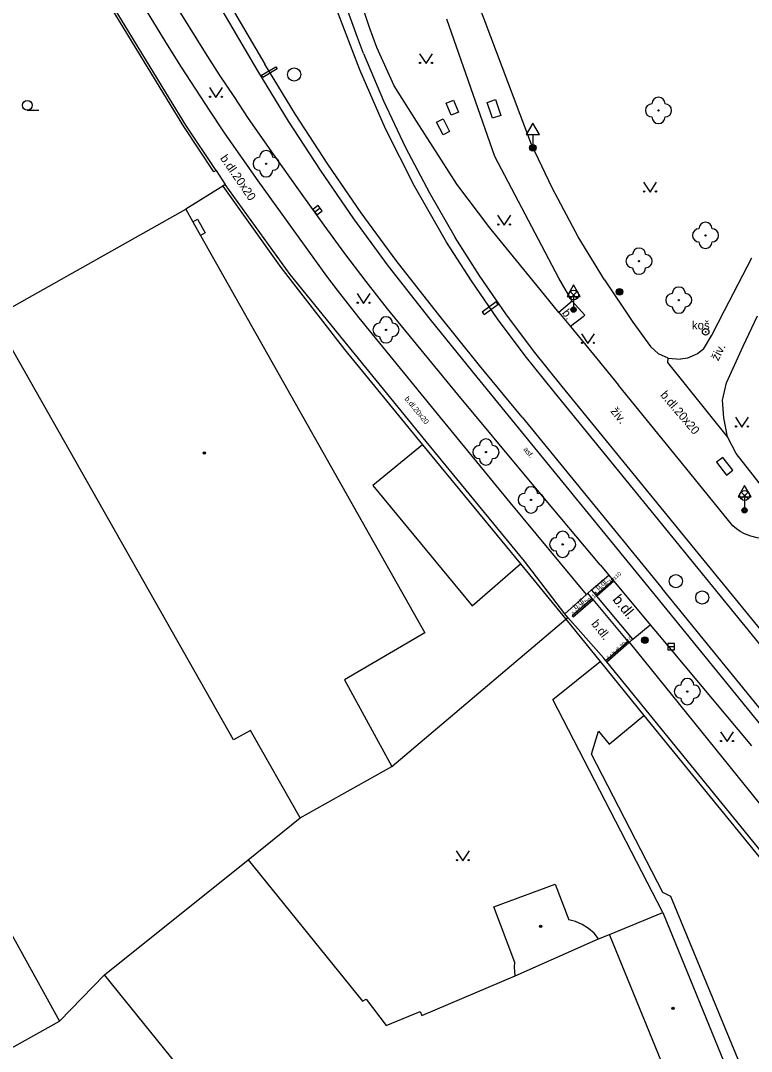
# Model space of a CAD drawing. Extents: x -600391 to -599491, y -1160176 to -1159402.
# Drawn here: x -599968.2 to -599912.4, y -1159894.2 to -1159815.5 of the extents above; entities that cross this region are included whole.
import ezdxf

# ---------------------------------------------------------------- set-up
doc = ezdxf.new("R2010")
doc.units = 0
for name, color, linetype in [('Level 10', 7, 'Continuous'), ('Level 11', 7, 'Continuous'), ('Level 13', 7, 'Continuous'), ('Level 22', 7, 'Continuous'), ('Level 24', 7, 'Continuous'), ('Level 25', 7, 'Continuous'), ('Level 26', 7, 'Continuous'), ('Level 27', 7, 'Continuous'), ('Level 33', 7, 'Continuous'), ('Level 34', 7, 'Continuous'), ('Level 36', 7, 'Continuous'), ('Level 39', 7, 'Continuous'), ('Level 40', 7, 'Continuous'), ('Level 42', 7, 'Continuous'), ('Level 5', 7, 'Continuous'), ('Level 7', 7, 'Continuous'), ('Level 8', 7, 'Continuous')]:
    doc.layers.add(name, color=color, linetype=linetype)

msp = doc.modelspace()

# ---------------------------------------------------------------- linework, layer by layer
at = {"layer": 'Level 10'}
for points in [[(-599936.04, -1159826.18), (-599937.94, -1159823.2), (-599939.66, -1159820.5), (-599940.98, -1159817.58), (-599941.54, -1159816.06), (-599942.03, -1159814.52), (-599942.52, -1159812.71), (-599943.22, -1159810.03), (-599943.39, -1159809.27), (-599943.93, -1159805.09)], [(-599950.76, -1159822.99), (-599951.87, -1159821.33), (-599952.97, -1159819.66), (-599954.05, -1159817.98), (-599956.51, -1159814.03)], [(-599944.99, -1159831.14), (-599945.71, -1159830.14), (-599946.93, -1159828.44), (-599948.85, -1159825.72), (-599950.76, -1159822.99)], [(-599928.52, -1159836.04), (-599932.34, -1159831.33), (-599934.86, -1159828.01), (-599936.04, -1159826.18)], [(-599940.15, -1159837.51), (-599941.8, -1159835.42), (-599943.42, -1159833.29), (-599944.99, -1159831.14)], [(-599927.08, -1159837.79), (-599928.52, -1159836.04)], [(-599923.93, -1159857.04), (-599929.38, -1159850.57), (-599934.79, -1159844.06), (-599940.15, -1159837.51)], [(-599923.93, -1159857.04), (-599929.38, -1159850.57), (-599934.79, -1159844.06), (-599940.15, -1159837.51)], [(-599927.08, -1159837.79), (-599926.2, -1159838.87)], [(-599926.2, -1159838.87), (-599924.2, -1159841.28), (-599922.53, -1159843.35)], [(-599916.76, -1159850.42), (-599922.53, -1159843.35)], [(-599913.81, -1159854.07), (-599916.76, -1159850.42)], [(-599912.92, -1159854.67), (-599913.24, -1159854.5), (-599913.53, -1159854.3), (-599913.81, -1159854.07)], [(-599912.44, -1159854.85), (-599912.92, -1159854.67)], [(-599911.43, -1159855.04), (-599911.56, -1159855.03), (-599911.94, -1159854.98), (-599912.44, -1159854.85)], [(-599923.93, -1159857.04), (-599923.27, -1159857.84), (-599922.94, -1159858.23), (-599922.88, -1159858.3), (-599920.11, -1159861.62)], [(-599920.11, -1159861.62), (-599919.42, -1159862.43)], [(-599919.42, -1159862.43), (-599912.37, -1159870.85)]]:
    msp.add_lwpolyline(points, dxfattribs=at)
at = {"layer": 'Level 11'}
for points in [[(-599963.14, -1159797.1), (-599955.3, -1159810.46), (-599950.08, -1159819.36)], [(-599929.17, -1159824.98), (-599933.64, -1159813.1), (-599938.33, -1159799.7)], [(-599955.87, -1159819.09), (-599956.94, -1159817.39), (-599958, -1159815.68), (-599959.04, -1159813.96), (-599965.39, -1159802.89)], [(-599941.98, -1159818.03), (-599942.44, -1159816.83), (-599942.88, -1159815.63), (-599943.31, -1159814.42)], [(-599931.96, -1159825.89), (-599935.62, -1159815.41)], [(-599941.98, -1159818.03), (-599940.46, -1159821.65), (-599938.79, -1159825.2), (-599936.96, -1159828.67), (-599935, -1159832.07)], [(-599952.59, -1159824.08), (-599953.7, -1159822.43), (-599954.79, -1159820.76), (-599955.87, -1159819.09)], [(-599950.08, -1159819.36), (-599947.75, -1159823.19), (-599945.31, -1159826.95), (-599942.76, -1159830.64), (-599940.11, -1159834.25)], [(-599949.78, -1159819.7), (-599948.67, -1159819.05)], [(-599949.68, -1159819.87), (-599949.78, -1159819.7)], [(-599948.57, -1159819.22), (-599949.68, -1159819.87)], [(-599948.67, -1159819.05), (-599948.57, -1159819.22)], [(-599943.98, -1159836.09), (-599944.78, -1159835.02), (-599947.42, -1159831.4), (-599950.02, -1159827.75), (-599952.59, -1159824.08)], [(-599923.59, -1159835.31), (-599925.62, -1159832.02), (-599927.59, -1159828.28), (-599929.17, -1159824.98)], [(-599927.08, -1159835.17), (-599931.96, -1159825.89)], [(-599952.73, -1159828.15), (-599955.55, -1159829.92)], [(-599955.01, -1159830.88), (-599954.66, -1159830.68)], [(-599954.66, -1159830.68), (-599954.07, -1159831.73)], [(-599954.07, -1159831.73), (-599954.42, -1159831.92)], [(-599926.82, -1159843.43), (-599929.02, -1159840.71), (-599931.12, -1159837.9), (-599933.11, -1159835.02), (-599935, -1159832.07)], [(-599915.4, -1159839.53), (-599914.44, -1159837.63), (-599912.35, -1159833.62)], [(-599940.11, -1159834.25), (-599936.92, -1159838.31), (-599933.68, -1159842.33), (-599930.41, -1159846.32)], [(-599926.06, -1159836.93), (-599927.08, -1159835.17)], [(-599923.59, -1159835.31), (-599921.43, -1159838.54)], [(-599942.33, -1159838.19), (-599943.16, -1159837.14), (-599943.98, -1159836.09)], [(-599931.87, -1159836.97), (-599932.93, -1159837.76)], [(-599931.72, -1159837.17), (-599931.87, -1159836.97)], [(-599926.06, -1159836.93), (-599927.08, -1159837.79)], [(-599926.06, -1159836.93), (-599925.1, -1159838), (-599925.23, -1159838.12)], [(-599932.93, -1159837.76), (-599932.78, -1159837.96)], [(-599932.78, -1159837.96), (-599931.72, -1159837.17)], [(-599924.98, -1159859.3), (-599930.79, -1159852.28), (-599936.57, -1159845.25), (-599942.33, -1159838.19)], [(-599925.23, -1159838.12), (-599926.2, -1159838.87)], [(-599921.43, -1159838.54), (-599920.09, -1159840.4)], [(-599914.29, -1159843.15), (-599913.03, -1159840.37), (-599911.92, -1159838.06)], [(-599916.04, -1159840.58), (-599915.4, -1159839.53)], [(-599918.73, -1159841.29), (-599919.47, -1159840.96), (-599920.09, -1159840.4)], [(-599916.04, -1159840.58), (-599916.5, -1159840.96), (-599917.26, -1159841.29), (-599917.8, -1159841.36)], [(-599914.22, -1159847.29), (-599918.76, -1159841.62), (-599918.73, -1159841.29)], [(-599918.73, -1159841.29), (-599917.8, -1159841.36)], [(-599914.22, -1159847.29), (-599914.5, -1159845.82), (-599914.6, -1159844.48), (-599914.29, -1159843.15)], [(-599878.58, -1159902.33), (-599881.68, -1159898.66), (-599890.08, -1159888.41), (-599897.94, -1159878.76), (-599907.81, -1159866.73), (-599916.46, -1159856.14), (-599926.82, -1159843.43)], [(-599930.41, -1159846.32), (-599919.73, -1159859.38), (-599911.26, -1159869.78), (-599901.58, -1159881.58), (-599893.26, -1159891.76), (-599885.63, -1159901.13), (-599882.18, -1159905.23)], [(-599937.5, -1159847.9), (-599941.28, -1159851), (-599933.71, -1159860.17), (-599930, -1159856.97)], [(-599913.55, -1159848.54), (-599914.22, -1159847.29)], [(-599909.94, -1159853.16), (-599913.55, -1159848.54)], [(-599924.98, -1159859.3), (-599924.87, -1159859.21), (-599924.58, -1159858.96), (-599923.27, -1159857.84)], [(-599924.98, -1159859.3), (-599924.87, -1159859.21), (-599924.58, -1159858.96), (-599923.27, -1159857.84)], [(-599922.94, -1159858.23), (-599924.24, -1159859.36)], [(-599922.94, -1159858.23), (-599924.24, -1159859.36)], [(-599921.44, -1159862.71), (-599924.18, -1159859.43), (-599924.24, -1159859.36), (-599924.58, -1159858.96)], [(-599924.18, -1159859.43), (-599922.88, -1159858.3)], [(-599924.18, -1159859.43), (-599922.88, -1159858.3)], [(-599924.98, -1159859.3), (-599926.62, -1159860.77)], [(-599924.54, -1159859.61), (-599926.06, -1159860.93)], [(-599926, -1159861.01), (-599924.47, -1159859.69)], [(-599921.74, -1159862.96), (-599921.8, -1159862.89), (-599924.47, -1159859.69), (-599924.54, -1159859.61), (-599924.87, -1159859.21)], [(-599939.83, -1159872.43), (-599926.54, -1159861.18)], [(-599926.54, -1159861.18), (-599926.4, -1159861.06)], [(-599926, -1159861.01), (-599926.06, -1159860.93)], [(-599899.77, -1159890.08), (-599904.44, -1159884.3), (-599914.02, -1159872.44), (-599921.7, -1159862.93), (-599921.44, -1159862.71), (-599920.11, -1159861.62)], [(-599899.77, -1159890.08), (-599904.44, -1159884.3), (-599914.02, -1159872.44), (-599921.7, -1159862.93), (-599921.44, -1159862.71), (-599920.11, -1159861.62)], [(-599921.8, -1159862.89), (-599923.49, -1159864.37)], [(-599923.43, -1159864.44), (-599921.74, -1159862.96), (-599921.7, -1159862.93)], [(-599919.16, -1159883.57), (-599927.54, -1159867.32), (-599923.93, -1159864.42)], [(-599913.1, -1159895.5), (-599918.54, -1159882.33), (-599919.14, -1159882.04), (-599924.58, -1159871.49), (-599924.05, -1159869.73), (-599923.24, -1159870.71), (-599920.59, -1159868.53)], [(-599950.79, -1159879.55), (-599946.83, -1159876.34)], [(-599965.19, -1159891.85), (-599961.76, -1159888.32)]]:
    msp.add_lwpolyline(points, dxfattribs=at)
at = {"layer": 'Level 13'}
for points in [[(-599954.67, -1159810.08), (-599949.51, -1159818.86)], [(-599935.65, -1159832.43), (-599938.09, -1159828.17), (-599940.3, -1159823.78), (-599942.28, -1159819.29), (-599944.02, -1159814.7)], [(-599939.5, -1159833.83), (-599942.16, -1159830.19), (-599944.72, -1159826.49), (-599947.17, -1159822.7), (-599949.51, -1159818.86)], [(-599931.76, -1159838.29), (-599933.76, -1159835.39), (-599935.65, -1159832.43)], [(-599929.89, -1159845.79), (-599933.14, -1159841.83), (-599936.34, -1159837.85), (-599939.5, -1159833.82)], [(-599927.44, -1159843.85), (-599929.65, -1159841.11), (-599931.76, -1159838.29)], [(-599882.25, -1159899.15), (-599890.61, -1159888.94), (-599898.53, -1159879.23), (-599908.38, -1159867.2), (-599917.02, -1159856.63), (-599927.45, -1159843.85)], [(-599929.89, -1159845.78), (-599919.19, -1159858.86)], [(-599901, -1159881.13), (-599910.7, -1159869.27), (-599919.19, -1159858.86)]]:
    msp.add_lwpolyline(points, dxfattribs=at)
at = {"layer": 'Level 22'}
for centre in [(-599919.48, -1159822.38), (-599949.42, -1159826.45), (-599915.89, -1159831.91), (-599920.96, -1159833.88), (-599917.93, -1159836.85), (-599940.27, -1159839.12), (-599932.65, -1159848.44), (-599929.2, -1159852.09), (-599926.79, -1159855.48), (-599917.28, -1159866.71)]:
    msp.add_circle(centre, 0.05, dxfattribs=at)
for centre, start, end in [((-599919.98, -1159822.38), 90, 270), ((-599919.48, -1159821.88), 0, 180), ((-599918.98, -1159822.38), 270, 90), ((-599919.48, -1159822.88), 180, 0), ((-599949.92, -1159826.45), 90, 270), ((-599949.42, -1159825.95), 0, 180), ((-599948.92, -1159826.45), 270, 90), ((-599949.42, -1159826.95), 180, 0), ((-599916.39, -1159831.91), 90, 270), ((-599915.89, -1159831.41), 0, 180), ((-599915.39, -1159831.91), 270, 90), ((-599920.96, -1159833.38), 0, 180), ((-599915.89, -1159832.41), 180, 0), ((-599921.46, -1159833.88), 90, 270), ((-599920.46, -1159833.88), 270, 90), ((-599920.96, -1159834.38), 180, 0), ((-599917.93, -1159836.35), 0, 180), ((-599918.43, -1159836.85), 90, 270), ((-599917.43, -1159836.85), 270, 90), ((-599917.93, -1159837.35), 180, 0), ((-599940.77, -1159839.12), 90, 270), ((-599940.27, -1159838.62), 0, 180), ((-599939.77, -1159839.12), 270, 90), ((-599940.27, -1159839.62), 180, 0), ((-599933.15, -1159848.44), 90, 270), ((-599932.65, -1159847.94), 0, 180), ((-599932.15, -1159848.44), 270, 90), ((-599932.65, -1159848.94), 180, 0), ((-599929.2, -1159851.59), 0, 180), ((-599929.7, -1159852.09), 90, 270), ((-599928.7, -1159852.09), 270, 90), ((-599929.2, -1159852.59), 180, 0), ((-599927.29, -1159855.48), 90, 270), ((-599926.79, -1159854.98), 0, 180), ((-599926.29, -1159855.48), 270, 90), ((-599926.79, -1159855.98), 180, 0), ((-599917.28, -1159866.21), 0, 180), ((-599917.78, -1159866.71), 90, 270), ((-599916.78, -1159866.71), 270, 90), ((-599917.28, -1159867.21), 180, 0)]:
    msp.add_arc(centre, 0.5, start, end, dxfattribs=at)
at = {"layer": 'Level 24'}
for points in [[(-599935.29, -1159822.74), (-599935.68, -1159821.82), (-599935.12, -1159821.59), (-599934.74, -1159822.51), (-599935.29, -1159822.74)], [(-599936.42, -1159823.28), (-599935.92, -1159823.02)], [(-599935.92, -1159824.24), (-599936.42, -1159823.28)], [(-599935.92, -1159823.02), (-599935.42, -1159823.98)], [(-599935.42, -1159823.98), (-599935.92, -1159824.24)]]:
    msp.add_lwpolyline(points, dxfattribs=at)
at = {"layer": 'Level 25'}
for centre, radius in [((-599929.07, -1159825.24), 0.25), ((-599929.07, -1159825.24), 0.2), ((-599929.07, -1159825.24), 0.15), ((-599929.07, -1159825.24), 0.1), ((-599929.07, -1159825.24), 0.05), ((-599922.45, -1159836.22), 0.25), ((-599922.45, -1159836.22), 0.2), ((-599922.45, -1159836.22), 0.15), ((-599922.45, -1159836.22), 0.1), ((-599922.45, -1159836.22), 0.05), ((-599915.88, -1159839.27), 0.25), ((-599915.88, -1159839.27), 0.0303), ((-599920.53, -1159862.79), 0.25), ((-599920.53, -1159862.79), 0.2), ((-599920.53, -1159862.79), 0.15), ((-599920.53, -1159862.79), 0.1), ((-599920.53, -1159862.79), 0.05)]:
    msp.add_circle(centre, radius, dxfattribs=at)
at = {"layer": 'Level 26'}
for points in [[(-599932.55, -1159821.78), (-599931.92, -1159821.56)], [(-599932.14, -1159822.98), (-599932.55, -1159821.78)], [(-599931.92, -1159821.56), (-599931.51, -1159822.76)], [(-599931.51, -1159822.76), (-599932.14, -1159822.98)], [(-599914.57, -1159848.85), (-599915.05, -1159849.22)], [(-599915.05, -1159849.22), (-599914.28, -1159850.2)], [(-599913.8, -1159849.83), (-599914.57, -1159848.85)], [(-599914.28, -1159850.2), (-599913.8, -1159849.83)]]:
    msp.add_lwpolyline(points, dxfattribs=at)
at = {"layer": 'Level 27'}
for p, q in [((-599945.301, -1159829.839), (-599945.699, -1159830.141)), ((-599918.77, -1159863.28), (-599918.27, -1159863.28))]:
    msp.add_line(p, q, dxfattribs=at)
for points in [[(-599945.452, -1159829.64), (-599945.85, -1159829.942), (-599945.548, -1159830.34), (-599945.15, -1159830.038)], [(-599918.77, -1159863.53), (-599918.27, -1159863.53), (-599918.27, -1159863.03), (-599918.77, -1159863.03)]]:
    msp.add_lwpolyline(points, close=True, dxfattribs=at)
for centre in [(-599947.28, -1159819.64), (-599918.16, -1159858.29), (-599916.14, -1159859.53)]:
    msp.add_circle(centre, 0.5, dxfattribs=at)
at = {"layer": 'Level 33'}
for p, q in [((-599926.225, -1159836.72), (-599925.695, -1159836.19)), ((-599926.225, -1159836.19), (-599925.695, -1159836.72)), ((-599925.96, -1159836.83), (-599925.96, -1159837.58)), ((-599913.175, -1159852.02), (-599912.645, -1159851.49)), ((-599913.175, -1159851.49), (-599912.645, -1159852.02)), ((-599912.91, -1159852.13), (-599912.91, -1159852.88))]:
    msp.add_line(p, q, dxfattribs=at)
for centre, radius in [((-599925.96, -1159836.455), 0.375), ((-599925.96, -1159837.58), 0.2), ((-599925.96, -1159837.58), 0.145), ((-599925.96, -1159837.58), 0.0876), ((-599912.91, -1159851.755), 0.375), ((-599912.91, -1159852.88), 0.2), ((-599912.91, -1159852.88), 0.145), ((-599912.91, -1159852.88), 0.0876)]:
    msp.add_circle(centre, radius, dxfattribs=at)
at = {"layer": 'Level 34'}
for p, q in [((-599929.07, -1159824.222), (-599929.07, -1159825.24)), ((-599929.32, -1159825.24), (-599928.82, -1159825.24)), ((-599925.96, -1159836.562), (-599925.96, -1159837.58)), ((-599912.91, -1159851.862), (-599912.91, -1159852.88))]:
    msp.add_line(p, q, dxfattribs=at)
for points in [[(-599929.57, -1159824.222), (-599928.57, -1159824.222), (-599929.07, -1159823.356)], [(-599926.46, -1159836.562), (-599925.46, -1159836.562), (-599925.96, -1159835.696)], [(-599913.41, -1159851.862), (-599912.41, -1159851.862), (-599912.91, -1159850.996)]]:
    msp.add_lwpolyline(points, close=True, dxfattribs=at)
at = {"layer": 'Level 36'}
msp.add_line((-599967.65, -1159822.365), (-599966.775, -1159822.365), dxfattribs=at)
for points in [[(-599937.72, -1159818.06), (-599937.22, -1159818.81), (-599936.72, -1159818.06)], [(-599953.75, -1159820.64), (-599953.25, -1159821.39), (-599952.75, -1159820.64)], [(-599920.62, -1159827.86), (-599920.12, -1159828.61), (-599919.62, -1159827.86)], [(-599931.76, -1159830.38), (-599931.26, -1159831.13), (-599930.76, -1159830.38)], [(-599942.48, -1159836.35), (-599941.98, -1159837.1), (-599941.48, -1159836.35)], [(-599925.36, -1159839.41), (-599924.86, -1159840.16), (-599924.36, -1159839.41)], [(-599913.61, -1159845.78), (-599913.11, -1159846.53), (-599912.61, -1159845.78)], [(-599914.75, -1159869.78), (-599914.25, -1159870.53), (-599913.75, -1159869.78)], [(-599934.91, -1159878.87), (-599934.41, -1159879.62), (-599933.91, -1159878.87)]]:
    msp.add_lwpolyline(points, dxfattribs=at)
for centre, radius in [((-599937.67, -1159818.76), 0.05), ((-599936.771, -1159818.76), 0.05), ((-599953.7, -1159821.34), 0.05), ((-599952.801, -1159821.34), 0.05), ((-599967.65, -1159821.99), 0.375), ((-599920.57, -1159828.56), 0.05), ((-599919.671, -1159828.56), 0.05), ((-599931.71, -1159831.08), 0.05), ((-599930.811, -1159831.08), 0.05), ((-599942.43, -1159837.05), 0.05), ((-599941.531, -1159837.05), 0.05), ((-599925.31, -1159840.11), 0.05), ((-599924.411, -1159840.11), 0.05), ((-599913.56, -1159846.48), 0.05), ((-599912.661, -1159846.48), 0.05), ((-599914.7, -1159870.48), 0.05), ((-599913.801, -1159870.48), 0.05), ((-599934.86, -1159879.57), 0.05), ((-599933.961, -1159879.57), 0.05)]:
    msp.add_circle(centre, radius, dxfattribs=at)
at = {"layer": 'Level 39'}
for centre, radius in [((-599954.13, -1159848.51), 0.09), ((-599954.13, -1159848.51), 0.0398), ((-599928.48, -1159884.62), 0.09), ((-599928.48, -1159884.62), 0.0398), ((-599918.38, -1159890.88), 0.09), ((-599918.38, -1159890.88), 0.0398)]:
    msp.add_circle(centre, radius, dxfattribs=at)
at = {"layer": 'Level 5'}
for points in [[(-599969.46, -1159837.75), (-599955.55, -1159829.92)], [(-599955.55, -1159829.92), (-599955.01, -1159830.88)], [(-599955.01, -1159830.88), (-599954.42, -1159831.92)], [(-599954.42, -1159831.92), (-599937.3, -1159862.24)], [(-599951.91, -1159870.4), (-599969.1, -1159840.07)], [(-599937.3, -1159862.24), (-599943.43, -1159865.82)], [(-599943.43, -1159865.82), (-599939.83, -1159872.43)], [(-599950.61, -1159869.69), (-599951.91, -1159870.4)], [(-599946.83, -1159876.34), (-599950.61, -1159869.69)], [(-599946.83, -1159876.34), (-599939.83, -1159872.43)], [(-599961.76, -1159888.32), (-599950.79, -1159879.55)], [(-599950.79, -1159879.55), (-599942.06, -1159890.32)], [(-599971.16, -1159881.07), (-599965.19, -1159891.85)], [(-599932.04, -1159883.12), (-599927.37, -1159881.39)], [(-599927.37, -1159881.39), (-599926.33, -1159884.12)], [(-599930.45, -1159887.37), (-599932.04, -1159883.12)], [(-599925.81, -1159884.25), (-599926.33, -1159884.12)], [(-599923.23, -1159885.24), (-599919.16, -1159883.57)], [(-599919.16, -1159883.57), (-599913.77, -1159896.69)], [(-599925.3, -1159884.47), (-599925.81, -1159884.25)], [(-599924.82, -1159884.77), (-599925.3, -1159884.47)], [(-599924.4, -1159885.14), (-599924.82, -1159884.77)], [(-599930.41, -1159888.39), (-599924.05, -1159885.57)], [(-599924.05, -1159885.57), (-599924.4, -1159885.14)], [(-599924.05, -1159885.57), (-599923.23, -1159885.24)], [(-599917.84, -1159898.37), (-599923.23, -1159885.24)], [(-599930.48, -1159887.74), (-599930.45, -1159887.37)], [(-599930.41, -1159888.39), (-599930.48, -1159887.74)], [(-599952.65, -1159899.58), (-599961.76, -1159888.32)], [(-599937.55, -1159891.43), (-599930.41, -1159888.39)], [(-599942.06, -1159890.32), (-599941.8, -1159890.17)], [(-599941.8, -1159890.17), (-599940.26, -1159892.19)], [(-599940.26, -1159892.19), (-599937.67, -1159891.12)], [(-599937.67, -1159891.12), (-599937.55, -1159891.43)], [(-599972.37, -1159895.85), (-599965.19, -1159891.85)]]:
    msp.add_lwpolyline(points, dxfattribs=at)
at = {"layer": 'Level 7'}
for points in [[(-599953.24, -1159826.96), (-599955.54, -1159823.5), (-599956.79, -1159821.48), (-599962.84, -1159811.54), (-599965.94, -1159806.1), (-599968.14, -1159802.38)], [(-599953.41, -1159827.07), (-599955.71, -1159823.61), (-599956.96, -1159821.58), (-599963.01, -1159811.64)], [(-599953.24, -1159826.96), (-599953.41, -1159827.07)], [(-599952.56, -1159828.04), (-599952.73, -1159828.15)], [(-599952.73, -1159828.15), (-599948.3, -1159834.36), (-599943.45, -1159840.61), (-599937.5, -1159847.9)], [(-599926.4, -1159861.06), (-599926.62, -1159860.77), (-599929.7, -1159856.77), (-599937.21, -1159847.64), (-599943.17, -1159840.34), (-599947.58, -1159834.89), (-599952.56, -1159828.04)], [(-599937.5, -1159847.9), (-599930, -1159856.97)], [(-599930, -1159856.97), (-599926.54, -1159861.18)], [(-599926.54, -1159861.18), (-599923.93, -1159864.42)], [(-599899.13, -1159895.39), (-599899.08, -1159894.99), (-599899.17, -1159894.48), (-599899.42, -1159893.99), (-599912.29, -1159878.13), (-599923.43, -1159864.44), (-599923.49, -1159864.37), (-599923.65, -1159864.17), (-599926.4, -1159861.06)], [(-599923.93, -1159864.42), (-599920.59, -1159868.53), (-599912.61, -1159878.32), (-599899.66, -1159894.2), (-599899.47, -1159894.52), (-599899.39, -1159894.94), (-599899.43, -1159895.22)]]:
    msp.add_lwpolyline(points, dxfattribs=at)
at = {"layer": 'Level 8'}
msp.add_lwpolyline([(-599953.24, -1159826.96), (-599952.56, -1159828.04)], dxfattribs=at)

# ---------------------------------------------------------------- texts
at = {"layer": 'Level 40'}
for s, height, rotation, p in [('b.dl.20x20', 0.65, 304.46315, (-599952.96, -1159826.03)), ('b.', 0.65, 307.71105, (-599926.88, -1159837.84)), ('živ.', 0.65, 63.3924, (-599914.92, -1159841.53)), ('b.dl.20x20', 0.65, 310.41856, (-599919.38, -1159844.11)), ('b.dl.20x20', 0.4, 309.17746, (-599938.88, -1159844.39)), ('živ.', 0.65, 309.06637, (-599923.18, -1159845.34)), ('asf.', 0.4, 309, (-599929.82, -1159848.24)), ('č.r.b.dl.20x10', 0.3, 41, (-599924.17, -1159859.4)), ('b.dl.', 0.4, 41, (-599924.09, -1159858.99)), ('č.r.b.dl.20x10', 0.3, 41, (-599925.93, -1159860.95)), ('b.dl.', 0.4, 41, (-599925.81, -1159860.46)), ('b.dl.', 0.8, 309.44512, (-599923.03, -1159859.71)), ('b.dl.', 0.65, 308.216, (-599924.64, -1159861.55)), ('č.r.b.dl.20x10', 0.3, 41, (-599923.31, -1159864.32))]:
    msp.add_text(s, height=height, rotation=rotation, dxfattribs=at).set_placement(p)
at = {"layer": 'Level 42'}
msp.add_text('koš', height=0.65, dxfattribs=at).set_placement((-599916.93, -1159839.09))

doc.saveas('drawing.dxf')
